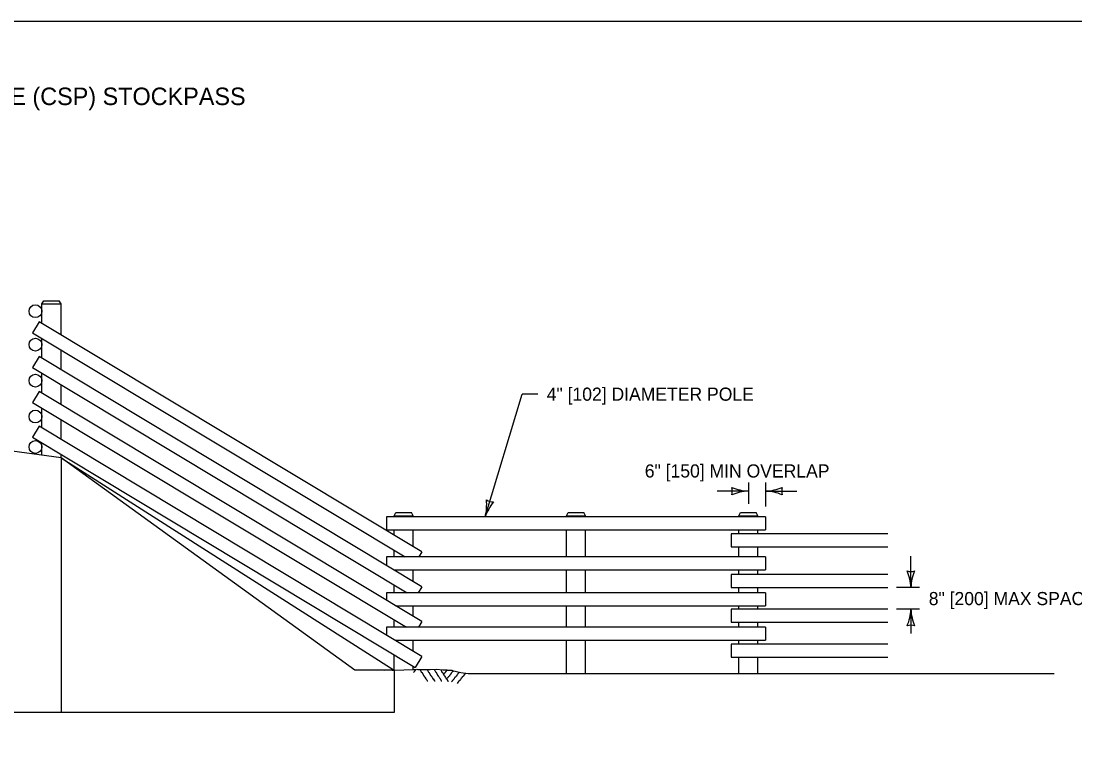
# Model space of a CAD drawing. Extents: x 49991 to 50288, y 49919 to 50011.
# Drawn here: x 50008.695 to 50013.515, y 49995.696 to 49998.999 of the extents above; entities that cross this region are included whole.
import ezdxf

# ---------------------------------------------------------------- set-up
doc = ezdxf.new("R2010")
doc.units = 0
for name, color, linetype in [('Level 1', 7, 'Continuous'), ('Level 2', 7, 'Continuous'), ('Level 3', 7, 'Continuous'), ('Level 5', 7, 'Continuous'), ('Level 7', 7, 'Continuous')]:
    doc.layers.add(name, color=color, linetype=linetype)

msp = doc.modelspace()

# ---------------------------------------------------------------- linework, layer by layer
at = {"layer": 'Level 1'}
for p, q in [((50010.2222, 49996.0323), (50008.8786, 49997.0034)), ((50008.8786, 49997.0034), (50008.8786, 49995.8391)), ((50010.4008, 49996.0323), (50010.2222, 49996.0323)), ((50010.4008, 49996.0323), (50010.4008, 49995.8391)), ((50010.4008, 49995.8391), (50008.5483, 49995.8391))]:
    msp.add_line(p, q, dxfattribs=at)
msp.add_lwpolyline([(49999.3835, 49998.9992), (50016.7501, 49998.9992), (50016.7501, 49987.7988), (49999.3835, 49987.7988)], close=True, dxfattribs=at)
msp.add_lwpolyline([(49999.3835, 49998.9992), (50016.7501, 49998.9992), (50016.7501, 49987.7988), (49999.3835, 49987.7988)], close=True, dxfattribs=at)
at = {"layer": 'Level 3'}
for p, q in [((50010.8177, 49996.7335), (50010.9865, 49997.2943)), ((50011.0592, 49997.2942), (50010.9865, 49997.2943)), ((50012.0211, 49996.8911), (50012.0211, 49996.7933)), ((50012.1002, 49996.8911), (50012.1002, 49996.7801)), ((50012.0211, 49996.8511), (50011.8782, 49996.8511)), ((50012.1002, 49996.8511), (50012.2431, 49996.8511)), ((50012.7644, 49996.4104), (50012.7644, 49996.5533)), ((50012.8044, 49996.4104), (50012.6986, 49996.4104)), ((50012.8044, 49996.3114), (50012.6986, 49996.3114)), ((50012.7644, 49996.3114), (50012.7644, 49996.1999))]:
    msp.add_line(p, q, dxfattribs=at)
for centre, radius, start, end in [((50012.0302, 49997.0733), 0.2223, 247.456, 267.6395), ((50011.8929, 49996.8511), 0.0548, 342.1388, 17.8612), ((50012.0326, 49996.6184), 0.233, 92.8273, 112.0772), ((50012.0887, 49997.0839), 0.233, 272.8273, 292.0772), ((50012.091, 49996.629), 0.2223, 67.456, 87.6395), ((50012.2284, 49996.8511), 0.0548, 162.1388, 197.8612), ((50010.5916, 49996.7896), 0.233, 346.0815, 5.3313), ((50011.0278, 49996.6608), 0.2223, 140.7102, 160.8937), ((50010.8547, 49996.8563), 0.0548, 235.393, 271.1153), ((50012.7644, 49996.5386), 0.0548, 252.1388, 287.8612), ((50012.5317, 49996.3989), 0.233, 2.8273, 22.0772), ((50012.9865, 49996.4013), 0.2223, 157.456, 177.6395), ((50012.5423, 49996.3205), 0.2223, 337.456, 357.6395), ((50012.9971, 49996.3229), 0.233, 182.8273, 202.0772), ((50012.7644, 49996.1832), 0.0548, 72.1388, 107.8612)]:
    msp.add_arc(centre, radius, start, end, dxfattribs=at)
at = {"layer": 'Level 5'}
for p, q in [((50008.8786, 49997.0034), (50008.5512, 49997.0476)), ((50008.8786, 49997.0034), (50010.4008, 49996.0323)), ((50010.6384, 49996.0334), (50010.649, 49996.0334)), ((50010.7401, 49996.0179), (50013.4201, 49996.0179))]:
    msp.add_line(p, q, dxfattribs=at)
for points in [[(50010.3567, 49996.0326), (50010.364, 49996.034), (50010.386, 49996.034), (50010.3927, 49996.0323), (50010.401, 49996.0323)], [(50010.401, 49996.0323), (50010.4906, 49996.0357), (50010.5007, 49996.0357), (50010.5058, 49996.0373), (50010.5092, 49996.0357), (50010.5615, 49996.0357), (50010.5666, 49996.0357), (50010.5953, 49996.0373), (50010.624, 49996.034), (50010.6425, 49996.034), (50010.6476, 49996.0323), (50010.6594, 49996.0323), (50010.6661, 49996.0323), (50010.6661, 49996.0306), (50010.7067, 49996.0222), (50010.7401, 49996.0179)], [(50010.4982, 49996.0361), (50010.4999, 49996.0344), (50010.4948, 49996.0277), (50010.4948, 49996.026), (50010.4931, 49996.026), (50010.4915, 49996.0226), (50010.4903, 49996.0214)], [(50010.5206, 49996.0357), (50010.5256, 49996.0239), (50010.529, 49996.0222), (50010.5357, 49996.0087), (50010.5375, 49996.0087), (50010.5391, 49996.0053), (50010.5391, 49996.0036), (50010.5425, 49996.0002), (50010.5459, 49995.9935), (50010.5476, 49995.9935), (50010.5527, 49995.9833), (50010.556, 49995.9833)], [(50010.5531, 49996.0361), (50010.5581, 49996.0243), (50010.5615, 49996.0226), (50010.5683, 49996.0091), (50010.57, 49996.0091), (50010.5716, 49996.0057), (50010.5716, 49996.004), (50010.575, 49996.0007), (50010.5784, 49995.9939), (50010.5801, 49995.9939), (50010.5852, 49995.9838), (50010.5885, 49995.9838)], [(50010.5847, 49996.0369), (50010.5898, 49996.0251), (50010.5932, 49996.0234), (50010.5999, 49996.01), (50010.6016, 49996.01), (50010.6033, 49996.0066), (50010.6033, 49996.0049), (50010.6067, 49996.0015), (50010.61, 49995.9947), (50010.6118, 49995.9947), (50010.6168, 49995.9846), (50010.6202, 49995.9846)], [(50010.6147, 49996.0353), (50010.6197, 49996.0234), (50010.6231, 49996.0217), (50010.6299, 49996.0083), (50010.6316, 49996.0083), (50010.6333, 49996.0049), (50010.6333, 49996.0032), (50010.6366, 49995.9998), (50010.64, 49995.9931), (50010.6417, 49995.9931), (50010.6468, 49995.9829), (50010.6501, 49995.9829)], [(50010.6431, 49996.032), (50010.64, 49996.0289), (50010.64, 49996.0272), (50010.6383, 49996.0272), (50010.6366, 49996.0239), (50010.6349, 49996.0239), (50010.6349, 49996.0222), (50010.6315, 49996.0188), (50010.6315, 49996.0171), (50010.6299, 49996.0171), (50010.6282, 49996.0138)], [(50010.6705, 49996.0278), (50010.6691, 49996.0264), (50010.6691, 49996.0247), (50010.6674, 49996.0247), (50010.6657, 49996.0214), (50010.6624, 49996.0196), (50010.6607, 49996.0146), (50010.6573, 49996.0129), (50010.6573, 49996.0112), (50010.6539, 49996.0078), (50010.6539, 49996.0061), (50010.6523, 49996.0061), (50010.6505, 49996.0028), (50010.6489, 49996.0028), (50010.6489, 49996.0011), (50010.6455, 49995.9977), (50010.6455, 49995.996), (50010.6438, 49995.996), (50010.6421, 49995.9926)], [(50010.6965, 49996.0243), (50010.6982, 49996.0226), (50010.6932, 49996.0159), (50010.6932, 49996.0142), (50010.6915, 49996.0142), (50010.6898, 49996.0108), (50010.6848, 49996.0057), (50010.6848, 49996.004), (50010.683, 49996.004), (50010.6814, 49996.0007), (50010.678, 49995.9989), (50010.6763, 49995.9939), (50010.6729, 49995.9922), (50010.6729, 49995.9905), (50010.6695, 49995.9872), (50010.6695, 49995.9855), (50010.6679, 49995.9855), (50010.6661, 49995.9821), (50010.6645, 49995.9821), (50010.6645, 49995.9804), (50010.664, 49995.9799)], [(50010.7248, 49996.0196), (50010.7265, 49996.0179), (50010.7214, 49996.0112), (50010.7214, 49996.0095), (50010.7198, 49996.0095), (50010.7181, 49996.0061), (50010.713, 49996.0011), (50010.713, 49995.9994), (50010.7113, 49995.9994), (50010.7096, 49995.996), (50010.7063, 49995.9944), (50010.7045, 49995.9892), (50010.7012, 49995.9876), (50010.7012, 49995.9859), (50010.6978, 49995.9825), (50010.6978, 49995.9808), (50010.6961, 49995.9808), (50010.6944, 49995.9774), (50010.6928, 49995.9774), (50010.6928, 49995.9758), (50010.6894, 49995.9724)]]:
    msp.add_lwpolyline(points, dxfattribs=at)
at = {"layer": 'Level 7'}
for p, q in [((50008.7906, 49997.7065), (50008.799, 49997.7211)), ((50008.7906, 49997.7065), (50008.8786, 49997.7065)), ((50008.7906, 49997.6178), (50008.7906, 49997.7065)), ((50008.799, 49997.7211), (50008.8702, 49997.7211)), ((50008.8786, 49997.7065), (50008.8702, 49997.7211)), ((50008.8786, 49997.5648), (50008.8786, 49997.7065)), ((50008.7777, 49997.6252), (50008.7474, 49997.5748)), ((50010.5283, 49996.573), (50008.7777, 49997.6252)), ((50008.7474, 49997.5748), (50010.4522, 49996.5502)), ((50008.7906, 49997.545), (50008.7906, 49997.5491)), ((50008.7906, 49997.4586), (50008.7906, 49997.545)), ((50008.7777, 49997.466), (50008.7474, 49997.4156)), ((50010.5283, 49996.4138), (50008.7777, 49997.466)), ((50008.8786, 49997.4056), (50008.8786, 49997.496)), ((50008.7474, 49997.4156), (50010.4607, 49996.3858)), ((50008.7906, 49997.299), (50008.7906, 49997.3899)), ((50008.8786, 49997.2461), (50008.8786, 49997.337)), ((50008.7777, 49997.3068), (50008.7474, 49997.2564)), ((50010.5283, 49996.2546), (50008.7777, 49997.3068)), ((50008.7474, 49997.2564), (50010.4574, 49996.2286)), ((50008.7906, 49997.1399), (50008.7906, 49997.2304)), ((50008.8786, 49997.0869), (50008.8786, 49997.1775)), ((50008.7777, 49997.1476), (50008.7474, 49997.0972)), ((50010.5283, 49996.0954), (50008.7777, 49997.1476)), ((50008.7474, 49997.0972), (50010.498, 49996.045)), ((50008.7906, 49997.0153), (50008.7906, 49997.0712)), ((50008.8786, 49997.0034), (50008.8786, 49997.0183)), ((50010.4008, 49996.7387), (50010.4093, 49996.7533)), ((50010.4008, 49996.7387), (50010.4889, 49996.7387)), ((50010.4008, 49996.7335), (50010.4008, 49996.7387)), ((50010.4093, 49996.7533), (50010.4805, 49996.7533)), ((50010.4889, 49996.7387), (50010.4805, 49996.7533)), ((50010.4889, 49996.7335), (50010.4889, 49996.7387)), ((50011.1889, 49996.7387), (50011.1974, 49996.7533)), ((50011.1889, 49996.7387), (50011.277, 49996.7387)), ((50011.1889, 49996.7335), (50011.1889, 49996.7387)), ((50011.1974, 49996.7533), (50011.2686, 49996.7533)), ((50011.277, 49996.7387), (50011.2686, 49996.7533)), ((50011.277, 49996.7335), (50011.277, 49996.7387)), ((50011.9771, 49996.7387), (50011.9855, 49996.7533)), ((50011.9771, 49996.7387), (50012.0651, 49996.7387)), ((50011.9771, 49996.7335), (50011.9771, 49996.7387)), ((50011.9855, 49996.7533), (50012.0567, 49996.7533)), ((50012.0651, 49996.7387), (50012.0567, 49996.7533)), ((50012.0651, 49996.7335), (50012.0651, 49996.7387)), ((50012.1002, 49996.7335), (50010.3658, 49996.7335)), ((50010.3658, 49996.7335), (50010.3658, 49996.6747)), ((50012.1002, 49996.7335), (50012.1002, 49996.6747)), ((50010.3658, 49996.6747), (50012.1002, 49996.6747)), ((50010.4008, 49996.65), (50010.4008, 49996.6747)), ((50010.4889, 49996.597), (50010.4889, 49996.6747)), ((50011.1889, 49996.5772), (50011.1889, 49996.6747)), ((50011.277, 49996.5502), (50011.277, 49996.6747)), ((50012.6586, 49996.6554), (50011.942, 49996.6554)), ((50011.942, 49996.6554), (50011.942, 49996.5965)), ((50011.9771, 49996.6554), (50011.9771, 49996.6747)), ((50012.0651, 49996.6554), (50012.0651, 49996.6747)), ((50011.942, 49996.5965), (50012.6586, 49996.5965)), ((50011.9771, 49996.5772), (50011.9771, 49996.5965)), ((50012.0651, 49996.5502), (50012.0651, 49996.5965)), ((50012.1002, 49996.5502), (50010.3658, 49996.5502)), ((50010.3658, 49996.5502), (50010.3658, 49996.5115)), ((50010.4008, 49996.5772), (50010.4008, 49996.5813)), ((50010.4008, 49996.5502), (50010.4008, 49996.5772)), ((50010.5283, 49996.573), (50010.5146, 49996.5502)), ((50011.189, 49996.5502), (50011.1889, 49996.5772)), ((50011.9771, 49996.5502), (50011.9771, 49996.5772)), ((50012.1002, 49996.5502), (50012.1002, 49996.4913)), ((50010.3994, 49996.4913), (50012.1002, 49996.4913)), ((50010.4008, 49996.4908), (50010.4008, 49996.4913)), ((50010.4889, 49996.4375), (50010.4889, 49996.4913)), ((50011.189, 49996.3858), (50011.189, 49996.4913)), ((50011.277, 49996.3858), (50011.277, 49996.4913)), ((50012.6586, 49996.4693), (50011.942, 49996.4693)), ((50011.942, 49996.4693), (50011.942, 49996.4104)), ((50011.9771, 49996.4693), (50011.9771, 49996.4913)), ((50012.0651, 49996.4693), (50012.0651, 49996.4913)), ((50010.4008, 49996.3858), (50010.4008, 49996.4221)), ((50010.5283, 49996.4138), (50010.5115, 49996.3858)), ((50011.942, 49996.4104), (50012.6586, 49996.4104)), ((50011.9771, 49996.3858), (50011.9771, 49996.4104)), ((50012.0651, 49996.3858), (50012.0651, 49996.4104)), ((50012.1002, 49996.3858), (50010.3658, 49996.3858)), ((50010.3658, 49996.3858), (50010.3658, 49996.3523)), ((50012.1002, 49996.3858), (50012.1002, 49996.327)), ((50010.4079, 49996.327), (50012.1002, 49996.327)), ((50010.4889, 49996.2783), (50010.4889, 49996.327)), ((50011.1891, 49996.2286), (50011.189, 49996.327)), ((50011.277, 49996.2543), (50011.277, 49996.327)), ((50012.6586, 49996.3114), (50011.942, 49996.3114)), ((50011.942, 49996.3114), (50011.942, 49996.2525)), ((50011.9772, 49996.3114), (50011.9771, 49996.327)), ((50012.0651, 49996.3114), (50012.0651, 49996.327)), ((50010.4008, 49996.2286), (50010.4008, 49996.2626)), ((50012.1002, 49996.2286), (50010.3658, 49996.2286)), ((50010.3658, 49996.2286), (50010.3658, 49996.1931)), ((50010.5283, 49996.2546), (50010.5127, 49996.2286)), ((50011.277, 49996.2286), (50011.277, 49996.2543)), ((50011.942, 49996.2525), (50012.6586, 49996.2525)), ((50011.9772, 49996.2286), (50011.9772, 49996.2525)), ((50012.0651, 49996.2286), (50012.0651, 49996.2543)), ((50012.1002, 49996.2286), (50012.1002, 49996.1698)), ((50010.4047, 49996.1698), (50012.1002, 49996.1698)), ((50010.4889, 49996.1191), (50010.4889, 49996.1698)), ((50011.1892, 49996.0179), (50011.1891, 49996.1698)), ((50011.277, 49996.0179), (50011.277, 49996.1698)), ((50011.9772, 49996.1512), (50011.9772, 49996.1698)), ((50012.0651, 49996.1512), (50012.0651, 49996.1698)), ((50012.6586, 49996.1512), (50011.942, 49996.1512)), ((50011.942, 49996.1512), (50011.942, 49996.0924)), ((50010.4008, 49996.0323), (50010.4008, 49996.1034)), ((50010.5283, 49996.0954), (50010.498, 49996.045)), ((50011.942, 49996.0924), (50012.6586, 49996.0924)), ((50011.9773, 49996.0181), (50011.9772, 49996.0924)), ((50012.0651, 49996.0179), (50012.0651, 49996.0924)), ((50010.4889, 49996.0356), (50010.4889, 49996.0505))]:
    msp.add_line(p, q, dxfattribs=at)
for centre in [(50008.7612, 49997.6732), (50008.7612, 49997.5205), (50008.7612, 49997.3562), (50008.7612, 49997.1918), (50008.7612, 49997.0529)]:
    msp.add_circle(centre, 0.0293, dxfattribs=at)

# ---------------------------------------------------------------- texts
at = {"layer": 'Level 2'}
for s, height, p in [('UPSLOPE FENCE LAYOUT AT CORRUGATED STEEL PIPE (CSP) STOCKPASS', 0.08, (50005.7632, 49998.6153)), ('4" [102] DIAMETER POLE', 0.06, (50011.0992, 49997.2642)), ('6" [150] MIN OVERLAP', 0.06, (50011.5476, 49996.9133)), ('8" [200] MAX SPACING', 0.06, (50012.8462, 49996.33))]:
    msp.add_text(s, height=height, dxfattribs=at).set_placement(p)

doc.saveas('drawing.dxf')
